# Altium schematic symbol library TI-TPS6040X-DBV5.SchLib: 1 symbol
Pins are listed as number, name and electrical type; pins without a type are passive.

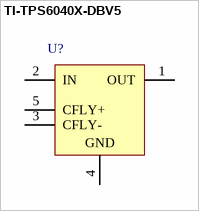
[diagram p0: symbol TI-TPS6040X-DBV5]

## TI-TPS6040X-DBV5
designator U?
TPS6040X Voltage Inverter
footprint TI-DBV5_N (SOT23, 5-Leads, Body 2.9x1.6mm, Pitch 0.95mm, IPC Medium Density)
pins: 1 OUT (power) "Power output with VO = -VI Bypass OUT to GND with the output filter capacitor CO", 2 IN (power) "Supply input. Connect to an input supply in the 1.6-V to 5.5-V range. Bypass IN to GND with a capacitor that has the same value as the flying capacitor", 3 CFLY- "Negative terminal of the flying capacitor C(fly)", 4 GND (power) "Ground", 5 CFLY+ "Positive terminal of the flying capacitor C(fly)"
